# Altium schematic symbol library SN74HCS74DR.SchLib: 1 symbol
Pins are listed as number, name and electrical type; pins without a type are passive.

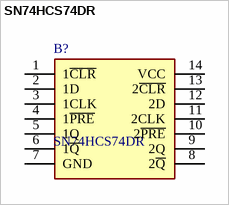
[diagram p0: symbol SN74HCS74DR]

## SN74HCS74DR
designator B?
Flip-Flops Schmitt-trigger input dual D-type positive-edge-triggered flip-flops w/ clear and preset 14-SOIC -40 to 125; Manufacturer_Name: Texas Instruments; Geometry.Height: 1.75mm
footprint SOIC127P600X175-14N
pins: 1 1~{CLR}, 2 1D, 3 1CLK, 4 1~{PRE}, 5 1Q, 6 1~{Q}, 7 GND, 8 2~{Q}, 9 2Q, 10 2~{PRE}, 11 2CLK, 12 2D, 13 2~{CLR}, 14 VCC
